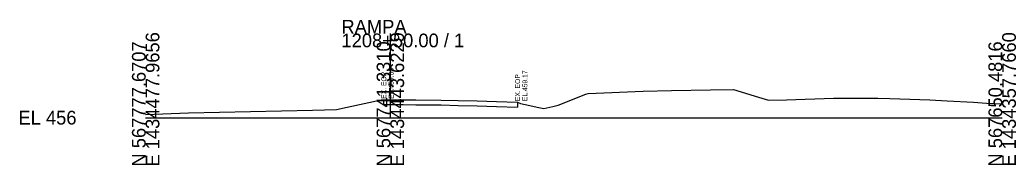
# Model space of a CAD drawing. Extents: x 1431908 to 1449087, y 567604 to 577825.
# Drawn here: x 1432908 to 1433111.5, y 574852.5 to 574882.1 of the extents above; entities that cross this region are included whole.
import ezdxf

# ---------------------------------------------------------------- set-up
doc = ezdxf.new("R2010")
doc.units = 0
for name, color, linetype in [('DESIGN - SHEET - Light Grid', 7, 'Continuous'), ('DESIGN - TYPICAL - Finished Grade and Subgrade', 7, 'Continuous'), ('SURVEY - GROUND - Existing Pavement Layer', 7, 'Continuous'), ('SURVEY - GROUND - Existing Pavement Text', 7, 'Continuous'), ('SURVEY - GROUND - Top of Ground', 7, 'Continuous')]:
    doc.layers.add(name, color=color, linetype=linetype)

msp = doc.modelspace()

# ---------------------------------------------------------------- linework, layer by layer
at = {"layer": 'DESIGN - SHEET - Light Grid'}
for p, q in [((1432983.66, 574862.16), (1432983.66, 574879.35)), ((1432933.66, 574862.16), (1432983.66, 574862.16)), ((1432983.66, 574862.16), (1433108.66, 574862.16))]:
    msp.add_line(p, q, dxfattribs=at)
at = {"layer": 'DESIGN - TYPICAL - Finished Grade and Subgrade'}
msp.add_line((1432982.31, 574865.82), (1432983.66, 574865.82), dxfattribs=at)
at = {"layer": 'SURVEY - GROUND - Existing Pavement Layer'}
for p, q in [((1432982.31, 574864.82), (1432982.31, 574865.82)), ((1432982.31, 574864.82), (1432983.66, 574864.82)), ((1432983.66, 574864.82), (1432985.37, 574864.82)), ((1432985.37, 574864.82), (1432986.26, 574864.83)), ((1432986.26, 574864.83), (1432988.88, 574864.8)), ((1432988.88, 574864.8), (1432994.07, 574864.76)), ((1432994.07, 574864.76), (1432997.49, 574864.68)), ((1432997.49, 574864.68), (1433001.39, 574864.59)), ((1433001.39, 574864.59), (1433005.35, 574864.46)), ((1433005.35, 574864.46), (1433009.65, 574864.33)), ((1433009.65, 574865.33), (1433009.65, 574864.33))]:
    msp.add_line(p, q, dxfattribs=at)
at = {"layer": 'SURVEY - GROUND - Top of Ground'}
msp.add_lwpolyline([(1432933.66, 574862.83), (1432942.41, 574863.15), (1432967.78, 574863.7), (1432972.65, 574863.84), (1432974.84, 574864.28), (1432981.8, 574865.78), (1432982.31, 574865.82), (1432983.66, 574865.82), (1432985.37, 574865.82), (1432986.26, 574865.83), (1432988.88, 574865.8), (1432994.07, 574865.76), (1432997.49, 574865.68), (1433001.39, 574865.59), (1433005.35, 574865.46), (1433009.65, 574865.33), (1433010.22, 574865.05), (1433011.18, 574864.85), (1433012.14, 574864.67), (1433013.62, 574864.34), (1433015.01, 574864.05), (1433016.83, 574864.46), (1433017.91, 574864.69), (1433023.6, 574866.94), (1433024.04, 574867.11), (1433035.3, 574867.58), (1433041.07, 574867.73), (1433049.09, 574867.83), (1433053.79, 574867.89), (1433058.84, 574866.36), (1433060.94, 574865.73), (1433064.57, 574865.83), (1433074.18, 574866.14), (1433079.1, 574866.15), (1433083.27, 574866.17), (1433085.7, 574866.08), (1433093.89, 574865.8), (1433097.43, 574865.6), (1433102.78, 574865.31), (1433105.48, 574865.11), (1433108.66, 574865)], dxfattribs=at)

# ---------------------------------------------------------------- texts
at = {"layer": 'DESIGN - SHEET - Light Grid'}
for s, p in [('RAMPA', (1432973.66, 574879.35)), ('1208+50.00 / 1', (1432973.66, 574876.55)), ('EL 456', (1432907.66, 574860.76))]:
    msp.add_text(s, height=2.8, dxfattribs=at).set_placement(p)
for s, p in [('E 1434477.9656', (1432936.46, 574852.16)), ('E 1434443.6229', (1432986.46, 574852.16)), ('E 1434357.7660', (1433111.46, 574852.16)), ('N 567777.6707', (1432933.66, 574852.16)), ('N 567741.3310', (1432983.66, 574852.16)), ('N 567650.4816', (1433108.66, 574852.16))]:
    msp.add_text(s, height=2.8, rotation=90, dxfattribs=at).set_placement(p)
at = {"layer": 'SURVEY - GROUND - Existing Pavement Text'}
for s, p in [('EL.459.66', (1432984.31, 574866.02)), ('EX. EOP', (1432982.81, 574866.02)), ('EX. EOP', (1433010.15, 574865.53)), ('EL.459.17', (1433011.65, 574865.53))]:
    msp.add_text(s, height=1, rotation=90, dxfattribs=at).set_placement(p)

doc.saveas('drawing.dxf')
